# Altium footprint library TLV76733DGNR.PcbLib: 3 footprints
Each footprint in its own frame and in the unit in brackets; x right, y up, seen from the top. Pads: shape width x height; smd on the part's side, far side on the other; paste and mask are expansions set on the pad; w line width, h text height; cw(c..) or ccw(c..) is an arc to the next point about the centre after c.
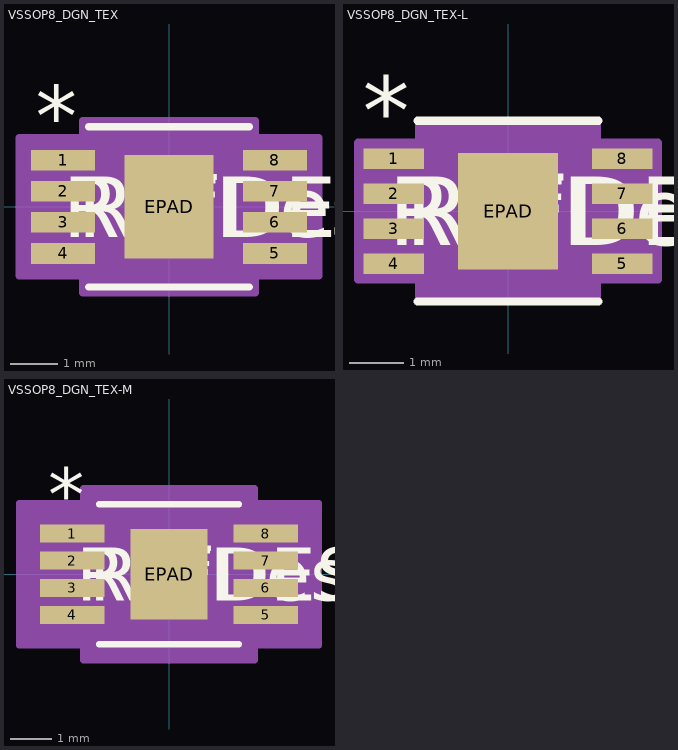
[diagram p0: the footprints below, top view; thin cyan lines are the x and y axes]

## VSSOP8_DGN_TEX [mil]
pads (9):
  rect 52.5x17 smd paste+0 mask+0: 1(-87.25,38.38) 2(-87.25,12.79) 3(-87.25,-12.79) 4(-87.25,-38.38) 5(87.25,-38.38) 6(87.25,-12.79) 7(87.25,12.79) 8(87.25,38.38)
  rect 73x85 smd paste+0 mask+0: EPAD(0,0)
Top Overlay:
  lines w6: -66,-66 66,-66 ; -66,66 66,66
  text "REFDES" at -87.5,-25 h50
  text "*" at -109.75,50.38 h50
  text "RefDes" at -75,-25 h50
Mechanical 13:
  lines w0: -12,61 ccw(c0,61) 12,61
  lines w1: -99.5,-45.88 -99.5,-30.89 -61,-30.89 -61,-45.88 -99.5,-45.88 ; -99.5,-20.3 -99.5,-5.29 -61,-5.29 -61,-20.3 -99.5,-20.3 ; -99.5,5.29 -99.5,20.3 -61,20.3 -61,5.29 -99.5,5.29 ; -99.5,30.89 -99.5,45.88 -61,45.88 -61,30.89 -99.5,30.89 ; -61,-61 61,-61 61,61 -61,61 -61,-61 ; 61,-45.88 61,-30.89 99.5,-30.89 99.5,-45.88 61,-45.88 ; 61,-20.3 61,-5.29 99.5,-5.29 99.5,-20.3 61,-20.3 ; 61,5.29 61,20.3 99.5,20.3 99.5,5.29 61,5.29 ; 61,30.89 61,45.88 99.5,45.88 99.5,30.89 61,30.89
  text "*" at -58.5,8 h50
  text "RefDes2" at -87.5,-25 h50
Mechanical 15:
  region: -71,-56.88 -123.5,-56.88 -123.5,56.88 -71,56.88 -71,71 71,71 71,56.88 123.5,56.88 123.5,-56.88 71,-56.88 71,-71 -71,-71
  lines w6: -123.5,-56.88 -123.5,56.88 -71,56.88 -71,71 71,71 71,56.88 123.5,56.88 123.5,-56.88 71,-56.88 71,-71 -71,-71 -71,-56.88 -123.5,-56.88
3D body "VSSOP8_DGN_TEX.step": height 43.11, standoff 0, extent -99.49,-60.98 99.49,60.98

## VSSOP8_DGN_TEX-L [mil]
pads (9):
  rect 44x15 smd paste+0 mask+0: 1(-83.5,38.38) 2(-83.5,12.79) 3(-83.5,-12.79) 4(-83.5,-38.38) 5(83.5,-38.38) 6(83.5,-12.79) 7(83.5,12.79) 8(83.5,38.38)
  rect 73x85 smd paste+0 mask+0: EPAD(0,0)
Top Overlay:
  lines w6: -66,-66 66,-66 ; -66,66 66,66
  text "REFDES" at -87.5,-25 h50
  text "*" at -106,48.38 h50
  text "RefDes" at -75,-25 h50
Mechanical 13:
  lines w0: -12,61 ccw(c0,61) 12,61
  lines w1: -99.5,-45.88 -99.5,-30.89 -61,-30.89 -61,-45.88 -99.5,-45.88 ; -99.5,-20.3 -99.5,-5.29 -61,-5.29 -61,-20.3 -99.5,-20.3 ; -99.5,5.29 -99.5,20.3 -61,20.3 -61,5.29 -99.5,5.29 ; -99.5,30.89 -99.5,45.88 -61,45.88 -61,30.89 -99.5,30.89 ; -61,-61 61,-61 61,61 -61,61 -61,-61 ; 61,-45.88 61,-30.89 99.5,-30.89 99.5,-45.88 61,-45.88 ; 61,-20.3 61,-5.29 99.5,-5.29 99.5,-20.3 61,-20.3 ; 61,5.29 61,20.3 99.5,20.3 99.5,5.29 61,5.29 ; 61,30.89 61,45.88 99.5,45.88 99.5,30.89 61,30.89
  text "*" at -58.5,8 h50
  text "RefDes2" at -87.5,-25 h50
Mechanical 15:
  region: -65,-49.88 -109.5,-49.88 -109.5,49.88 -65,49.88 -65,65 65,65 65,49.88 109.5,49.88 109.5,-49.88 65,-49.88 65,-65 -65,-65
  lines w6: -109.5,-49.88 -109.5,49.88 -65,49.88 -65,65 65,65 65,49.88 109.5,49.88 109.5,-49.88 65,-49.88 65,-65 -65,-65 -65,-49.88 -109.5,-49.88
3D body "VSSOP8_DGN_TEX.step": height 43.11, standoff 0, extent -99.49,-60.98 99.49,60.98

## VSSOP8_DGN_TEX-M [mil]
pads (9):
  rect 60.5x17 smd paste+0 mask+0: 1(-91.25,38.38) 2(-91.25,12.79) 3(-91.25,-12.79) 4(-91.25,-38.38) 5(91.25,-38.38) 6(91.25,-12.79) 7(91.25,12.79) 8(91.25,38.38)
  rect 73x85 smd paste+0 mask+0: EPAD(0,0)
Top Overlay:
  lines w6: -66,-66 66,-66 ; -66,66 66,66
  text "REFDES" at -87.5,-25 h50
  text "*" at -113.75,50.38 h50
  text "RefDes" at -75,-25 h50
Mechanical 13:
  lines w0: -12,61 ccw(c0,61) 12,61
  lines w1: -99.5,-45.88 -99.5,-30.89 -61,-30.89 -61,-45.88 -99.5,-45.88 ; -99.5,-20.3 -99.5,-5.29 -61,-5.29 -61,-20.3 -99.5,-20.3 ; -99.5,5.29 -99.5,20.3 -61,20.3 -61,5.29 -99.5,5.29 ; -99.5,30.89 -99.5,45.88 -61,45.88 -61,30.89 -99.5,30.89 ; -61,-61 61,-61 61,61 -61,61 -61,-61 ; 61,-45.88 61,-30.89 99.5,-30.89 99.5,-45.88 61,-45.88 ; 61,-20.3 61,-5.29 99.5,-5.29 99.5,-20.3 61,-20.3 ; 61,5.29 61,20.3 99.5,20.3 99.5,5.29 61,5.29 ; 61,30.89 61,45.88 99.5,45.88 99.5,30.89 61,30.89
  text "*" at -58.5,8 h50
  text "RefDes2" at -87.5,-25 h50
Mechanical 15:
  region: -81,-66.89 -141.5,-66.89 -141.5,66.89 -81,66.89 -81,81 81,81 81,66.89 141.5,66.89 141.5,-66.89 81,-66.89 81,-81 -81,-81
  lines w6: -141.5,-66.89 -141.5,66.89 -81,66.89 -81,81 81,81 81,66.89 141.5,66.89 141.5,-66.89 81,-66.89 81,-81 -81,-81 -81,-66.89 -141.5,-66.89
3D body "VSSOP8_DGN_TEX.step": height 43.11, standoff 0, extent -99.49,-60.98 99.49,60.98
